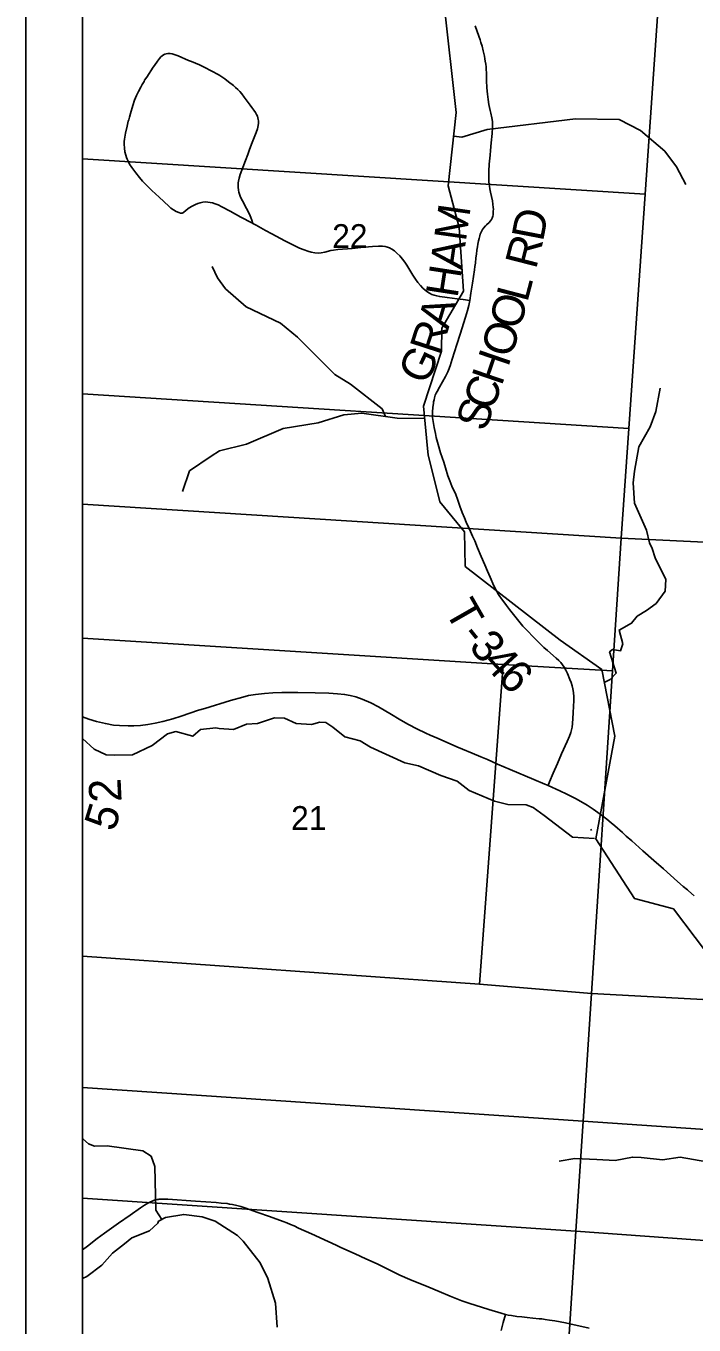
# Model space of a CAD drawing. Extents: x 0 to 34, y 0 to 22.
# Drawn here: x 2 to 3.179, y 17.749 to 20.043 of the extents above; entities that cross this region are included whole.
import ezdxf

# ---------------------------------------------------------------- set-up
doc = ezdxf.new("R2010")
doc.units = 0
for name, color, linetype in [('Default', 7, 'Continuous'), ('GM_X_County_Road', 7, 'Continuous'), ('GM_X_Minor_River', 7, 'Continuous'), ('GM_X_Section', 7, 'Continuous'), ('GM_X_Section_Text', 7, 'Continuous'), ('GM_X_State_Route', 7, 'Continuous'), ('GM_X_Township_Road', 7, 'Continuous'), ('GM_X_Township_Road_Text', 7, 'Continuous'), ('SH_Data', 7, 'Continuous'), ('SH_Text', 7, 'Continuous')]:
    doc.layers.add(name, color=color, linetype=linetype)

msp = doc.modelspace()

# ---------------------------------------------------------------- linework, layer by layer
at = {"layer": 'Default'}
msp.add_lwpolyline([(6.0603, 16.8624), (6.127, 17.9511), (6.1612, 18.4732), (6.1665, 18.5542), (6.1773, 18.7192), (6.1898, 18.9313), (6.195, 19.011), (6.2406, 19.7849), (6.241, 19.7927), (6.2413, 19.8018), (6.2418, 19.8127), (6.2424, 19.8289), (6.2426, 19.8432), (6.2426, 19.8474), (6.2427, 19.8586), (6.2428, 19.8591), (6.2428, 19.8627), (6.2428, 19.867), (6.2428, 19.8705), (6.2431, 19.8748), (6.2438, 19.8792), (6.3032, 20.9), (2.1, 20.9), (2.1, 16.1239)], dxfattribs=at)
for points in [[(2.1, 20.233), (2.1, 19.8081), (3.093, 19.7459), (3.1221, 20.1708)], [(2.1, 19.8081), (2.1, 19.3932), (3.0637, 19.3317), (3.093, 19.7459)], [(2.1, 19.3932), (2.1, 19.1986), (3.0501, 19.1382), (3.0637, 19.3317)], [(2.1, 19.1986), (2.1, 18.962), (2.8423, 18.9151), (3.0349, 18.9043), (3.0501, 19.1382)], [(2.1, 18.962), (2.1, 18.4005), (2.8005, 18.351), (2.8423, 18.9151)], [(2.1, 18.4005), (2.1, 18.1686), (2.9831, 18.1092), (2.9978, 18.3347), (2.8005, 18.351)], [(2.1, 18.1686), (2.1, 17.973), (2.9705, 17.9146), (2.9831, 18.1092)], [(2.1, 17.973), (2.1, 17.5604), (2.9438, 17.505), (2.9705, 17.9146)]]:
    msp.add_lwpolyline(points, close=True, dxfattribs=at)
at = {"layer": 'GM_X_County_Road'}
for points in [[(2.1, 17.8817), (2.1084, 17.8884), (2.1256, 17.9017), (2.1385, 17.9114), (2.1632, 17.9292), (2.1837, 17.9433), (2.2022, 17.9559), (2.2094, 17.9606), (2.2153, 17.9643), (2.2198, 17.9667), (2.2225, 17.9679), (2.2248, 17.9688), (2.2285, 17.97), (2.2309, 17.9706), (2.233, 17.9709), (2.2348, 17.9711), (2.2365, 17.9713), (2.2384, 17.9714), (2.2412, 17.9715), (2.2423, 17.9715), (2.2469, 17.9713), (2.2504, 17.9711), (2.2994, 17.9679), (2.3354, 17.9653), (2.3443, 17.9645), (2.355, 17.9634), (2.3594, 17.9627), (2.3644, 17.9618), (2.3718, 17.9601), (2.3789, 17.9581), (2.3861, 17.9559), (2.409, 17.948), (2.4295, 17.9407), (2.4541, 17.9319), (2.4605, 17.9295), (2.4669, 17.9268), (2.4733, 17.924), (2.481, 17.9204), (2.5036, 17.9099), (2.5335, 17.8963), (2.5475, 17.8899), (2.5555, 17.8862), (2.5807, 17.8748), (2.5998, 17.866), (2.6197, 17.8569), (2.6364, 17.8487), (2.6502, 17.8417), (2.6598, 17.8373), (2.6775, 17.8297), (2.7111, 17.8158), (2.7292, 17.8085), (2.7486, 17.8003), (2.7694, 17.7921), (2.7817, 17.7879), (2.8166, 17.7767), (2.8384, 17.7699), (2.8462, 17.7678)], [(2.8462, 17.7678), (2.8512, 17.7668), (2.857, 17.7657), (2.8661, 17.7643), (2.8749, 17.7633), (2.8845, 17.7623), (2.8944, 17.7613), (2.9057, 17.7603), (2.9104, 17.7598), (2.9164, 17.7591), (2.9238, 17.7579), (2.9333, 17.7564), (2.9522, 17.7529), (2.9595, 17.7514), (2.994, 17.7433)]]:
    msp.add_lwpolyline(points, dxfattribs=at)
at = {"layer": 'GM_X_Minor_River'}
for points in [[(3.2192, 18.3825), (3.1427, 18.4839), (3.0741, 18.5019), (3.0055, 18.6075), (3.0392, 18.7885), (3.0164, 18.9063), (2.9428, 18.9584), (2.7752, 19.0886), (2.774, 19.1496), (2.7304, 19.2028), (2.71, 19.2853), (2.7087, 19.2967), (2.7013, 19.3714), (2.7334, 19.4688), (2.7336, 19.509), (2.7719, 19.5747), (2.7643, 19.6869), (2.7451, 19.7604), (2.7594, 19.8899), (2.7374, 20.0852)], [(2.7548, 19.8482), (2.7693, 19.8466), (2.8139, 19.8601), (2.9699, 19.8788), (3.0466, 19.8774), (3.0847, 19.8583), (3.1275, 19.8216), (3.148, 19.794), (3.1643, 19.763)], [(2.6343, 19.3533), (2.6288, 19.3667), (2.5728, 19.4104), (2.5453, 19.4275), (2.4794, 19.493), (2.4489, 19.5177), (2.3886, 19.5467), (2.3522, 19.5783), (2.3377, 19.5979), (2.3288, 19.6182)], [(3.0217, 18.8844), (3.0311, 18.8886), (3.0418, 18.9), (3.03, 18.9376), (3.035, 18.9418), (3.0494, 18.9395), (3.0532, 18.9517), (3.0467, 18.976), (3.0687, 18.9882), (3.0786, 19.0004), (3.0953, 19.0107), (3.1123, 19.0232), (3.1282, 19.0449), (3.129, 19.0654), (3.1101, 19.1038), (3.1052, 19.1202), (3.1006, 19.1304), (3.0949, 19.1525), (3.0737, 19.2), (3.0715, 19.2361), (3.0737, 19.2566), (3.0817, 19.2996), (3.1018, 19.3349), (3.1117, 19.3619), (3.1189, 19.403)], [(2.7034, 19.3497), (2.6551, 19.3504), (2.5926, 19.3592), (2.561, 19.3559), (2.5156, 19.342), (2.4539, 19.3322), (2.3893, 19.3046), (2.3413, 19.2927), (2.3267, 19.283), (2.2888, 19.257), (2.2761, 19.221)], [(2.6683, 18.7418), (2.6077, 18.7691), (2.5899, 18.7805), (2.5626, 18.7877), (2.5414, 18.8044), (2.5289, 18.8127), (2.5186, 18.8135), (2.5038, 18.8096), (2.4769, 18.8111), (2.4561, 18.8206), (2.4383, 18.821), (2.4083, 18.8114), (2.3894, 18.8099), (2.3662, 18.8007), (2.3412, 18.8026), (2.3348, 18.8037), (2.3079, 18.8003), (2.2942, 18.7885), (2.2643, 18.7968), (2.2499, 18.793), (2.2229, 18.7724), (2.1877, 18.7561), (2.1555, 18.7553), (2.1414, 18.7556), (2.1206, 18.7659), (2.1, 18.7845)], [(3.0033, 18.6081), (2.9647, 18.6102), (2.9143, 18.6485), (2.895, 18.6626), (2.8829, 18.6675), (2.8506, 18.6679), (2.8268, 18.6743), (2.7824, 18.6929), (2.7612, 18.7096), (2.7324, 18.7194), (2.6926, 18.7365), (2.6683, 18.7418)], [(2.9966, 18.6247), (2.9978, 18.6225)], [(2.2395, 17.9355), (2.2291, 17.952), (2.2276, 18.0288), (2.2208, 18.047), (2.2064, 18.0569), (2.1431, 18.0652), (2.1207, 18.0648), (2.1101, 18.0693), (2.1003, 18.0781), (2.1, 18.0792)], [(3.6669, 17.7983), (3.621, 17.8285), (3.5903, 17.8501), (3.5702, 17.8627), (3.5531, 17.8645), (3.5395, 17.8737), (3.5209, 17.8961), (3.4561, 17.9401), (3.4322, 17.9538), (3.383, 17.9689), (3.3602, 17.9795), (3.3394, 18), (3.3117, 18.0107), (3.2787, 18.0239), (3.2295, 18.0322), (3.2249, 18.033), (3.1544, 18.0455), (3.1233, 18.0409), (3.0854, 18.0446), (3.0703, 18.0457), (3.0396, 18.0396), (3.0073, 18.0415), (2.9687, 18.0434), (2.941, 18.0384)], [(2.4432, 17.7451), (2.4402, 17.7876), (2.4269, 17.831), (2.4133, 17.8587), (2.3833, 17.8971), (2.3735, 17.9069), (2.3341, 17.9324), (2.311, 17.9403), (2.2784, 17.9445), (2.2461, 17.9391), (2.2336, 17.9322), (2.2325, 17.9288), (2.2177, 17.9155), (2.187, 17.9033), (2.1737, 17.8923), (2.1529, 17.8759), (2.1339, 17.8549), (2.1074, 17.8348), (2.1, 17.8313)]]:
    msp.add_lwpolyline(points, dxfattribs=at)
at = {"layer": 'GM_X_Section'}
for points in [[(3.1221, 20.1708), (4.1536, 20.1097), (4.1266, 19.6923), (4.0998, 19.2759), (4.0875, 19.0909), (4.0872, 19.0874), (3.4908, 19.1174), (3.0501, 19.1382), (3.0637, 19.3317), (3.093, 19.7459)], [(3.0501, 19.1382), (3.4908, 19.1174), (3.4459, 18.3102), (2.9978, 18.3347), (3.0349, 18.9043)], [(3.0349, 18.9043), (2.9978, 18.3347), (2.8005, 18.351), (2.8423, 18.9151)], [(3.4459, 18.3102), (3.9669, 18.2803), (3.9498, 18.0434), (2.9831, 18.1092), (2.9978, 18.3347)], [(2.9831, 18.1092), (3.9498, 18.0434), (4.0202, 18.0387), (4.01, 17.8394), (2.9705, 17.9146)], [(4.01, 17.8394), (3.9833, 17.4262), (2.9438, 17.505), (2.9705, 17.9146)]]:
    msp.add_lwpolyline(points, close=True, dxfattribs=at)
at = {"layer": 'GM_X_State_Route'}
for points in [[(2.1, 18.823), (2.1108, 18.819), (2.1243, 18.8146), (2.1402, 18.8109), (2.1542, 18.8084), (2.1652, 18.8075), (2.1802, 18.8068), (2.1901, 18.807), (2.202, 18.8077), (2.215, 18.8092), (2.2279, 18.8115), (2.2413, 18.8145), (2.2593, 18.8196), (2.2741, 18.8242), (2.3047, 18.8345), (2.3154, 18.8379), (2.3612, 18.8517), (2.3826, 18.8578), (2.3929, 18.8603), (2.4051, 18.8623), (2.421, 18.8643), (2.4359, 18.8654), (2.4513, 18.8659), (2.4799, 18.8657), (2.5103, 18.8654), (2.5345, 18.8647), (2.55, 18.8638), (2.5623, 18.8624), (2.572, 18.8607), (2.5822, 18.8581), (2.5933, 18.8543), (2.6087, 18.8479), (2.6219, 18.8403), (2.6449, 18.827), (2.6588, 18.8187), (2.6654, 18.8148), (2.6752, 18.8093), (2.69, 18.8017), (2.7055, 18.7942), (2.7133, 18.7906), (2.7272, 18.7845), (2.7601, 18.7702), (2.7704, 18.7657), (2.7876, 18.7585), (2.8025, 18.7523), (2.8145, 18.7473), (2.8319, 18.7396), (2.8542, 18.7302), (2.8964, 18.7122), (2.9158, 18.704), (2.9213, 18.7016), (2.9424, 18.692), (2.9543, 18.6866), (2.9698, 18.6788), (2.979, 18.6737), (2.9901, 18.6669), (3.001, 18.6598), (3.0131, 18.6512), (3.0248, 18.6421), (3.0325, 18.6358), (3.0391, 18.6302), (3.0526, 18.6184), (3.0593, 18.6125)], [(3.0593, 18.6125), (3.069, 18.604), (3.0886, 18.5865), (3.1081, 18.5693), (3.1249, 18.5543), (3.1499, 18.5321), (3.1596, 18.5236), (3.1672, 18.5175), (3.1693, 18.5156), (3.1791, 18.5071)]]:
    msp.add_lwpolyline(points, dxfattribs=at)
at = {"layer": 'GM_X_Township_Road'}
for points in [[(2.9213, 18.7016), (2.9239, 18.708), (2.9304, 18.7234), (2.9378, 18.7405), (2.9453, 18.7576), (2.955, 18.7791), (2.9591, 18.7888), (2.9614, 18.7952), (2.9626, 18.8), (2.9636, 18.8048), (2.9642, 18.8109), (2.9655, 18.8295), (2.9665, 18.8425), (2.9668, 18.8505), (2.9667, 18.858), (2.966, 18.866), (2.9652, 18.8721), (2.9639, 18.8775), (2.962, 18.8833), (2.9598, 18.8891), (2.9554, 18.8994), (2.9525, 18.9055), (2.9498, 18.9104), (2.9467, 18.915), (2.9437, 18.9189), (2.9404, 18.9225), (2.9359, 18.9267), (2.9202, 18.9399), (2.9136, 18.9456), (2.9051, 18.9539), (2.8964, 18.9627), (2.8839, 18.9757), (2.8771, 18.983), (2.8695, 18.992), (2.8535, 19.0127), (2.8482, 19.0195), (2.8413, 19.0283), (2.8392, 19.0313), (2.8349, 19.0373), (2.8335, 19.0394), (2.8307, 19.0442), (2.8258, 19.0543), (2.819, 19.0697), (2.8143, 19.0803), (2.8096, 19.091), (2.8032, 19.1057), (2.7969, 19.1213), (2.792, 19.1334), (2.7882, 19.1419), (2.7843, 19.1503), (2.782, 19.1554), (2.7768, 19.1667), (2.7736, 19.1741), (2.77, 19.1834), (2.7658, 19.1951), (2.7617, 19.2072), (2.7584, 19.2154), (2.7518, 19.2301), (2.7478, 19.2393), (2.7447, 19.2487), (2.7406, 19.2624), (2.7372, 19.2723), (2.7342, 19.2805), (2.7317, 19.2888), (2.7273, 19.3037), (2.7241, 19.3163), (2.7226, 19.323), (2.7204, 19.3338), (2.7186, 19.3441), (2.7176, 19.3516), (2.7173, 19.3561), (2.7172, 19.3614), (2.7179, 19.3688), (2.719, 19.3769), (2.7194, 19.3793), (2.7201, 19.3828), (2.721, 19.3859), (2.7222, 19.3907), (2.7237, 19.3944), (2.7255, 19.3976), (2.7298, 19.4049), (2.7403, 19.4239), (2.7444, 19.4322), (2.7457, 19.435), (2.7486, 19.4425), (2.7524, 19.4542), (2.7603, 19.4804), (2.766, 19.4988), (2.7758, 19.5283), (2.7792, 19.5402), (2.7815, 19.5492), (2.7822, 19.5523), (2.7831, 19.5582), (2.7853, 19.5708), (2.7881, 19.5886), (2.7917, 19.6123), (2.7924, 19.6179), (2.7931, 19.6241), (2.7941, 19.6333), (2.7949, 19.6397), (2.7958, 19.6466), (2.7967, 19.6525), (2.7974, 19.6573), (2.7985, 19.6632), (2.7996, 19.6676), (2.8008, 19.6721), (2.8018, 19.6752), (2.8028, 19.6775), (2.8043, 19.6807), (2.8057, 19.6831), (2.8073, 19.6854), (2.8111, 19.6897), (2.8129, 19.6916), (2.8174, 19.6958), (2.8198, 19.6985), (2.8215, 19.701), (2.8226, 19.7031), (2.8233, 19.7049), (2.8238, 19.7066), (2.8243, 19.7095), (2.8246, 19.7131), (2.8247, 19.7158), (2.8248, 19.7192), (2.8246, 19.7224), (2.824, 19.7278), (2.823, 19.7339), (2.8214, 19.7418), (2.8199, 19.7491), (2.8187, 19.7552), (2.8178, 19.7601), (2.817, 19.7675), (2.8167, 19.7731), (2.8167, 19.7764), (2.8167, 19.7794), (2.8169, 19.7862), (2.8177, 19.7985), (2.818, 19.8041), (2.8191, 19.8148), (2.8198, 19.8226), (2.8212, 19.8362), (2.8227, 19.8529), (2.8233, 19.8635), (2.8233, 19.8684), (2.823, 19.8739), (2.822, 19.8806), (2.8202, 19.889), (2.8191, 19.8932), (2.818, 19.8987), (2.8168, 19.9042), (2.8154, 19.9128), (2.8143, 19.922), (2.8135, 19.9332), (2.8129, 19.9463), (2.8125, 19.9605), (2.8123, 19.9655), (2.8119, 19.9706), (2.8115, 19.9753), (2.8106, 19.9807), (2.8098, 19.9846), (2.809, 19.9893), (2.8079, 19.9938), (2.8068, 19.9987), (2.8048, 20.007), (2.8029, 20.0134), (2.8013, 20.0183), (2.7963, 20.033), (2.7929, 20.043)], [(2.4005, 19.694), (2.4, 19.6958), (2.3988, 19.7), (2.397, 19.7047), (2.3944, 19.7103), (2.3892, 19.7202), (2.382, 19.7339), (2.3788, 19.7406), (2.3767, 19.7458), (2.3756, 19.7494), (2.3748, 19.753), (2.3743, 19.7579), (2.3742, 19.7629), (2.3746, 19.766), (2.375, 19.7684), (2.3762, 19.7739), (2.3782, 19.7804), (2.3825, 19.7927), (2.3871, 19.8049), (2.3914, 19.8159), (2.3947, 19.8246), (2.3993, 19.8368), (2.4062, 19.8548), (2.4084, 19.8613), (2.4097, 19.8667), (2.4103, 19.871), (2.4102, 19.8754), (2.4098, 19.8778), (2.4093, 19.8803), (2.4083, 19.8832), (2.4067, 19.8865), (2.4048, 19.8897), (2.4021, 19.8938), (2.3984, 19.8989), (2.3955, 19.9029), (2.3853, 19.917), (2.3808, 19.9229), (2.3776, 19.9267), (2.3737, 19.9307), (2.37, 19.934), (2.3663, 19.9373), (2.3575, 19.9442), (2.351, 19.9491), (2.3423, 19.955), (2.3391, 19.9568), (2.3281, 19.9631), (2.3145, 19.97), (2.3062, 19.9739), (2.2993, 19.9768), (2.2918, 19.9798), (2.2866, 19.9819), (2.2685, 19.99), (2.2615, 19.9925), (2.2579, 19.9934), (2.2542, 19.9939), (2.2505, 19.9939), (2.2474, 19.9935), (2.2451, 19.9928), (2.2429, 19.9917), (2.2403, 19.99), (2.238, 19.988), (2.2355, 19.9853), (2.2319, 19.9803), (2.2267, 19.9728), (2.2246, 19.9698), (2.2131, 19.9523), (2.2094, 19.9467), (2.2083, 19.9445), (2.2053, 19.9391), (2.2026, 19.9344), (2.1985, 19.9269), (2.1961, 19.9221), (2.195, 19.92), (2.1914, 19.9115), (2.1883, 19.9022), (2.1843, 19.8881), (2.1826, 19.8815), (2.1812, 19.8768), (2.1806, 19.8744), (2.1788, 19.8659), (2.1759, 19.8535), (2.1738, 19.8431), (2.1733, 19.8389), (2.1733, 19.834), (2.1738, 19.8267), (2.1747, 19.8206), (2.176, 19.8147), (2.1773, 19.8106), (2.1784, 19.8077), (2.1801, 19.8038), (2.1828, 19.7989), (2.1867, 19.7927), (2.1937, 19.7832), (2.2001, 19.7749), (2.2059, 19.7685), (2.2145, 19.7597), (2.222, 19.7523), (2.235, 19.7402), (2.252, 19.7243), (2.2559, 19.7212), (2.2604, 19.7181), (2.2652, 19.7154), (2.2697, 19.7133), (2.2726, 19.7123), (2.2739, 19.7121), (2.2754, 19.7122), (2.2766, 19.7127), (2.2777, 19.7134), (2.2826, 19.7173), (2.2882, 19.7213), (2.2934, 19.7246), (2.299, 19.7275), (2.303, 19.7291), (2.3071, 19.7305), (2.312, 19.7315), (2.317, 19.7319), (2.3207, 19.7317), (2.325, 19.7312), (2.3293, 19.7302), (2.334, 19.7287), (2.3392, 19.7266), (2.3459, 19.7232), (2.3602, 19.7156), (2.3793, 19.7053), (2.3986, 19.695), (2.4005, 19.694), (2.4064, 19.6908), (2.4227, 19.6817), (2.4336, 19.6757), (2.4566, 19.6635), (2.4721, 19.6556), (2.4828, 19.6506), (2.4908, 19.6472), (2.4973, 19.645), (2.5034, 19.6434), (2.5096, 19.6423), (2.5158, 19.6418), (2.5208, 19.6422), (2.5275, 19.6436), (2.5378, 19.6461), (2.5426, 19.6469), (2.5505, 19.6479), (2.5757, 19.65), (2.591, 19.6514), (2.6118, 19.6534), (2.6222, 19.6541), (2.6289, 19.6541), (2.6337, 19.6535), (2.6378, 19.6524), (2.6417, 19.6509), (2.6459, 19.6486), (2.6503, 19.6454), (2.6545, 19.6418), (2.6597, 19.6366), (2.6645, 19.631), (2.6686, 19.6257), (2.672, 19.6206), (2.6827, 19.6027), (2.6873, 19.5954), (2.6913, 19.5899), (2.6961, 19.5842), (2.7004, 19.5798), (2.7045, 19.5761), (2.7089, 19.5727), (2.7121, 19.5707), (2.716, 19.5688), (2.7201, 19.5673), (2.7249, 19.566), (2.7303, 19.5649), (2.7431, 19.5631), (2.7608, 19.5609), (2.7718, 19.5596), (2.7831, 19.5582)], [(2.8385, 17.7393), (2.8424, 17.7536), (2.8462, 17.7678)]]:
    msp.add_lwpolyline(points, dxfattribs=at)
at = {"layer": 'SH_Data'}
for p, q in [((2, 21), (2, 14)), ((2.1, 20.9), (2.1, 14.1))]:
    msp.add_line(p, q, dxfattribs=at)
at = {"layer": 'SH_Text'}
msp.add_lwpolyline([(8.9, 20.9), (2.1, 20.9), (2.1, 14.1)], dxfattribs=at)

# ---------------------------------------------------------------- texts
at = {"layer": 'GM_X_Section_Text'}
for s, p in [('22', (2.5404, 19.6509)), ('21', (2.4679, 18.6234))]:
    msp.add_text(s, height=0.04186, rotation=0, dxfattribs=at).set_placement(p)
at = {"layer": 'GM_X_Township_Road_Text'}
for s, rotation, p in [('M', 81.8979, (2.7762, 19.6608)), ('D', 79.1067, (2.9123, 19.6606)), ('A', 81.8963, (2.7691, 19.6113)), ('R', 75.6263, (2.8999, 19.6117)), ('H', 81.2444, (2.7614, 19.5612)), ('L', 75.2987, (2.8846, 19.5533)), ('O', 74.8704, (2.8714, 19.5046)), ('A', 73.2367, (2.7451, 19.5049)), ('R', 71.9795, (2.7302, 19.4592)), ('O', 72.949, (2.8562, 19.4548)), ('G', 64.7106, (2.706, 19.4067)), ('H', 71.0631, (2.8393, 19.4056)), ('C', 70.3553, (2.8234, 19.3609)), ('S', 70.2337, (2.8104, 19.3247)), ('T', 299.8135, (2.7379, 19.0102)), ('-', 308.9568, (2.7646, 18.9652)), ('3', 309.8645, (2.7799, 18.9463)), ('4', 312.7083, (2.8043, 18.9171)), ('6', 315.1743, (2.8299, 18.8895)), ('2', 92.7229, (2.1689, 18.6732)), ('5', 72.8422, (2.1559, 18.6185))]:
    msp.add_text(s, height=0.0568, rotation=rotation, dxfattribs=at).set_placement(p)

doc.saveas('drawing.dxf')
